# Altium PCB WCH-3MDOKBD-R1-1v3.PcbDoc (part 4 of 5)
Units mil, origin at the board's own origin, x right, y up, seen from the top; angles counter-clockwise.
Board outline 11710.74 x 4477.49 mil, 2 copper layers (Top Layer, Bottom Layer); 422 components, 246 nets, 927 pads, 1295 vias.
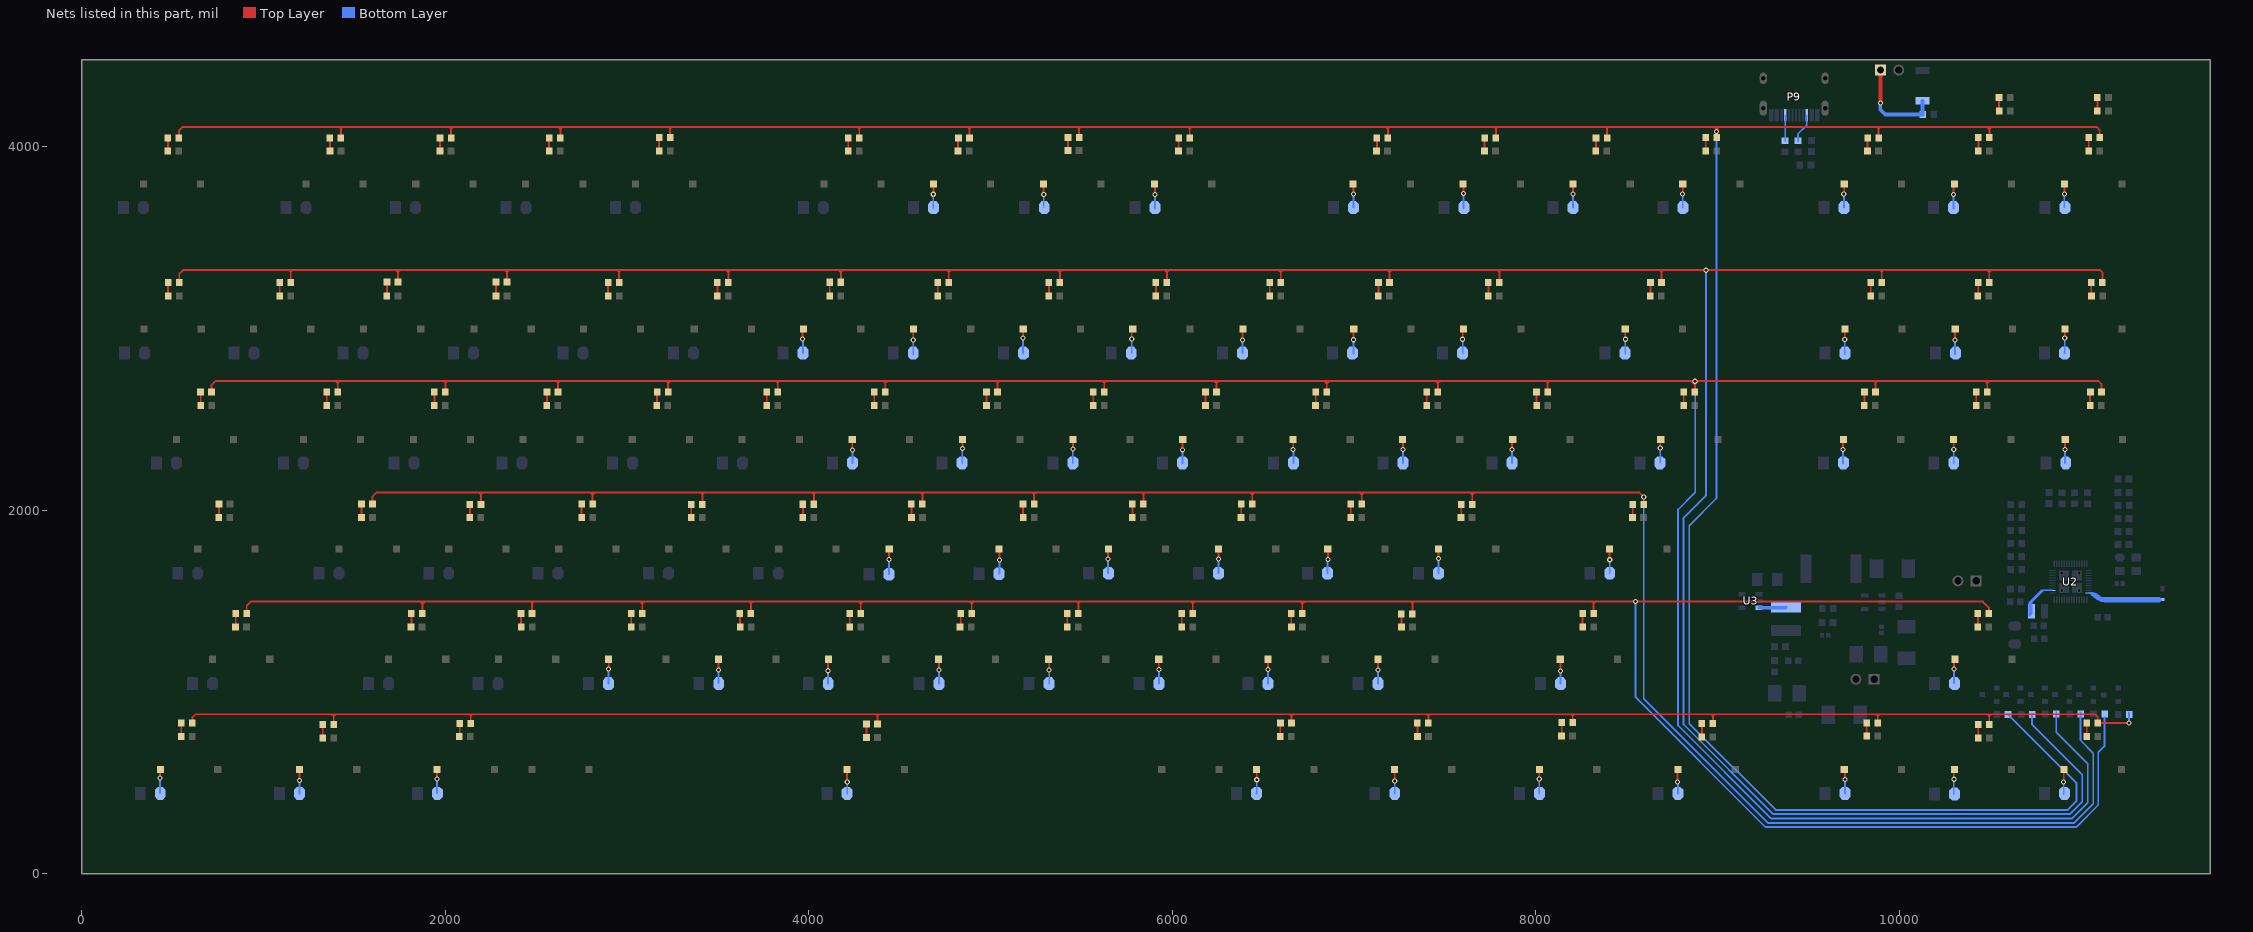
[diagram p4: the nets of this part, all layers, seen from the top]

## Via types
v1: diameter 28, hole 16, Top Layer to Bottom Layer, tented both sides, 1167 vias
v2: diameter 24, hole 12, Top Layer to Bottom Layer, tented both sides, 128 vias

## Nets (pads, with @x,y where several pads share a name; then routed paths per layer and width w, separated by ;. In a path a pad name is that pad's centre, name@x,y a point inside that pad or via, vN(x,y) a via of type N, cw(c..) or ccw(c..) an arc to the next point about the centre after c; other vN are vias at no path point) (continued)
NetD31_1: D31.1 S28.2 | length 134.2
  Top Layer w10: S28.2@2899.53,1178.83 2899.59,1178.76 v1(2899.59,1125.29)
  Bottom Layer w10: D31.1@2898.24,1045.22 2898.24,1123.94 v1(2899.59,1125.29)
NetD32_1: D32.1 S29.2 | length 132.2
  Top Layer w10: v1(3503.65,1120.09) 3503.65,1178.34 S29.2@3504.14,1178.83
  Bottom Layer w10: D32.1@3503.65,1046.84 v1(3503.65,1120.09)
NetD33_1: D33.1 S30.2 | length 131.7
  Top Layer w10: v1(4106.44,1116.13) S30.2@4106.44,1176.51
  Bottom Layer w10: v1(4106.44,1116.13) 4106.44,1046.21 D33.1@4107.43,1045.22
NetD34_1: D34.1 S31.2 | length 141.6
  Top Layer w10: v1(430.8,524.84) S31.2@430.8,584.45
  Bottom Layer w10: D34.1@430.8,442.82 v1(430.8,524.84)
NetD35_1: D35.1 S32.2 | length 152.1
  Top Layer w10: v1(1199.17,511.16) S32.2@1199.17,576.44
  Bottom Layer w10: D35.1@1198.31,440.87 1198.31,519.24 1199.17,518.39 v1(1199.17,511.16)
NetD36_1: D36.1 S33.2 | length 136.4
  Top Layer w10: v1(1955.94,519.52) S33.2@1955.94,578.37
  Bottom Layer w10: D36.1@1955.94,441.98 v1(1955.94,519.52)
NetD37_1: D37.1 S34.2 | length 132.3
  Top Layer w10: S34.2@4211.04,573.38 4211.04,504.55 v1(4211.82,503.77)
  Bottom Layer w10: D37.1@4211.82,441.42 v1(4211.82,503.77)
NetD38_1: D38.1 S35.2 | length 138.5
  Top Layer w10: v1(6464.36,516.16) S35.2@6464.36,579.19
  Bottom Layer w10: D38.1@6464.02,440.87 6464.36,441.22 v1(6464.36,516.16)
NetD39_1: D39.1 S_Fn1.2 | length 129
  Top Layer w10: v1(7223.58,510.3) S_Fn1.2@7223.58,569.84
  Bottom Layer w10: D39.1@7223.58,440.87 v1(7223.58,510.3)
NetD40_1: D40.1 S36.2 | length 132.3
  Top Layer w10: v1(4685.16,3736.92) 4685.86,3737.61 S36.2@4685.86,3793.97
  Bottom Layer w10: D40.1@4685.16,3661.95 v1(4685.16,3736.92)
NetD41_1: D41.1 S37.2 | length 129.4
  Top Layer w10: S37.2@5292.31,3794.25 5292.31,3736.51 v1(5293,3735.82)
  Bottom Layer w10: D41.1@5293,3665.15 v1(5293,3735.82)
NetD42_1: D42.1 S38.2 | length 138.5
  Top Layer w10: v1(5905.07,3735.23) S38.2@5905.07,3796.54
  Bottom Layer w10: D42.1@5905.07,3658.01 D42.1@5905.07,3664.02 v1(5905.07,3735.23)
NetD43_1: D43.1 S39.2 | length 131.5
  Top Layer w10: v1(6997.07,3739.18) S39.2@6997.07,3795.1
  Bottom Layer w10: D43.1@6995.94,3664.02 6995.94,3738.05 v1(6997.07,3739.18)
NetD44_1: D44.1 S40.2 | length 135.5
  Top Layer w10: v1(7601.65,3740.67) S40.2@7601.65,3797.73
  Bottom Layer w10: D44.1@7601.65,3662.26 v1(7601.65,3740.67)
NetD45_1: D45.1 S41.2 | length 130.1
  Top Layer w10: S41.2@8204.62,3793.88 8205.12,3793.38 v1(8205.12,3739.5)
  Bottom Layer w10: v1(8205.12,3739.5) 8205.12,3664.13 D45.1@8205.22,3664.02
NetD46_1: D46.1 S42.2 | length 130.5
  Top Layer w10: v1(8807.11,3739.5) 8807.58,3739.98 S42.2@8807.58,3793.8
  Bottom Layer w10: v1(8807.11,3739.5) 8808.27,3738.34 D46.1@8808.27,3664.02
NetD47_1: D47.1 S43.2 | length 134.3
  Top Layer w10: v1(3966,2941.18) S43.2@3966,2996.88
  Bottom Layer w10: v1(3966,2941.18) 3968.09,2939.09 D47.1@3968.09,2863.47
NetD48_1: D48.1 S44.2 | length 138
  Top Layer w10: v1(4574.85,2936.23) S44.2@4574.85,2992.51
  Bottom Layer w10: D48.1@4574.85,2854.52 D48.1@4574.85,2863.47 v1(4574.85,2936.23)
NetD49_1: D49.1 S45.2 | length 132.2
  Top Layer w10: v1(5179.6,2945.87) 5180.45,2946.72 S45.2@5180.45,2994.96
  Bottom Layer w10: v1(5179.6,2945.87) 5179.6,2864.34 D49.1@5180.47,2863.47
NetD50_1: D50.1 S46.2 | length 132.7
  Top Layer w10: v1(5776.74,2941.88) S46.2@5776.74,2994.99
  Bottom Layer w10: D50.1@5776.74,2862.31 v1(5776.74,2941.88)
NetD51_1: D51.1 S47.2 | length 139.1
  Top Layer w10: v1(6386.92,2936.4) S47.2@6386.92,3002.61
  Bottom Layer w10: D51.1@6386.92,2863.47 v1(6386.92,2936.4)
NetD52_1: D52.1 S48.2 | length 131.6
  Top Layer w10: v1(6996.14,2936.51) S48.2@6996.14,2993.09
  Bottom Layer w10: D52.1@6996.14,2861.45 v1(6996.14,2936.51)
NetD53_1: D53.1 S49.2 | length 134.9
  Top Layer w10: v1(7597.41,2939.64) S49.2@7597.41,2998.3
  Bottom Layer w10: D53.1@7597.3,2863.47 7597.41,2863.58 v1(7597.41,2939.64)
NetD54_1: D54.1 S50.2 | length 129.8
  Top Layer w10: S50.2@4239.53,2388.74 4239.53,2330.43 v1(4240.01,2329.95)
  Bottom Layer w10: D54.1@4239.96,2259.16 4240.01,2259.21 v1(4240.01,2329.95)
NetD55_1: D55.1 S51.2 | length 136.4
  Top Layer w10: v1(4845.53,2338.81) 4846.37,2339.65 S51.2@4846.37,2388.74 S51.2@4846.37,2394.62
  Bottom Layer w10: D55.1@4844.14,2259.16 4844.14,2337.42 v1(4845.53,2338.81)
NetD56_1: D56.1 S52.2 | length 129.1
  Top Layer w10: v1(5454.29,2335.45) S52.2@5454.29,2387.68
  Bottom Layer w10: D56.1@5452.8,2259.16 5452.8,2333.96 v1(5454.29,2335.45)
NetD57_1: D57.1 S53.2 | length 132
  Top Layer w10: v1(6055.6,2331.35) S53.2@6055.6,2391.13
  Bottom Layer w10: D57.1@6055.6,2259.16 v1(6055.6,2331.35)
NetD58_1: D58.1 S54.2 | length 130.5
  Top Layer w10: S54.2@6664.28,2388.74 6664.94,2388.08 v1(6664.94,2332.01)
  Bottom Layer w10: v1(6664.94,2332.01) 6666.44,2330.51 D58.1@6666.44,2259.16
NetD59_1: D59.1 S55.2 | length 133.2
  Top Layer w10: v1(7269,2331.93) S55.2@7269,2392.28
  Bottom Layer w10: v1(7269,2331.93) 7269,2259.3 D59.1@7269.14,2259.16
NetD60_1: D60.1 S56.2 | length 136.9
  Top Layer w10: S56.2@7869.08,2390.47 v1(7869.08,2333.53) v1@7873.05,2337.49
  Bottom Layer w10: D60.1@7869.08,2259.16 7869.08,2281.77 v1(7869.08,2333.53)
NetD61_1: D61.1 S57.2 | length 140.1
  Top Layer w10: v1(4442.36,1726.86) S57.2@4442.36,1786.71
  Bottom Layer w10: D61.1@4442.3,1646.61 4442.3,1726.8 v1(4442.36,1726.86)
NetD62_1: D62.1 S58.2 | length 137.8
  Top Layer w10: v1(5048.62,1725.98) S58.2@5048.62,1787.21
  Bottom Layer w10: D62.1@5047.11,1650.08 5048.62,1651.59 v1(5048.62,1725.98)
NetD63_1: D63.1 S59.2 | length 138.9
  Top Layer w10: v1(5646.28,1731) S59.2@5646.28,1793.07
  Bottom Layer w10: D63.1@5646.28,1654.16 v1(5646.28,1731)
NetD64_1: D64.1 S60.2 | length 133.9
  Top Layer w10: S60.2@6253.89,1785.35 6254.37,1784.87 v1(6254.37,1730.62)
  Bottom Layer w10: D64.1@6253.38,1652.04 6254.37,1653.03 v1(6254.37,1730.62)
NetD65_1: D65.1 S61.2 | length 133.7
  Top Layer w10: S61.2@6855.58,1785.35 6856.19,1784.74 v1(6856.19,1728.46)
  Bottom Layer w10: D65.1@6854.15,1651.91 v1@6854.15,1728.46
NetD66_1: D66.1 S62.2 | length 134.1
  Top Layer w10: S62.2@7464,1785.35 7464.51,1784.84 v1(7464.51,1732.79)
  Bottom Layer w10: D66.1@7463.53,1651.91 7464.51,1652.89 v1(7464.51,1732.79)
NetD67_1: D67.1 S63.2 | length 129
  Top Layer w10: v1(8684.1,2341.25) S63.2@8684.1,2390.07
  Bottom Layer w10: D67.1@8684.1,2261.08 v1(8684.1,2341.25)
NetD68_1: D68.1 S64.2 | length 138.3
  Top Layer w10: v1(4717.14,1120.08) S64.2@4717.14,1183.5
  Bottom Layer w10: D68.1@4717.14,1045.22 v1(4717.14,1120.08)
NetD69_1: D69.1 S65.2 | length 135.2
  Top Layer w10: v1(5322.73,1120.41) S65.2@5322.73,1180.38
  Bottom Layer w10: D69.1@5322.73,1045.22 v1(5322.73,1120.41)
NetD70_1: D70.1 S66.2 | length 134.1
  Top Layer w10: S66.2@5925.44,1178.83 5925.44,1124.13 v1(5926.55,1123.02)
  Bottom Layer w10: D70.1@5926.55,1045.22 v1(5926.55,1123.02)
NetD71_1: D71.1 S67.2 | length 133.9
  Top Layer w10: v1(6526.43,1122.05) S67.2@6526.44,1178.83
  Bottom Layer w10: D71.1@6525.65,1045.22 6526.43,1046 v1(6526.43,1122.05)
NetD72_1: D72.1 S68.2 | length 139.9
  Top Layer w10: v1(7131.13,1120.14) S68.2@7131.13,1179.43
  Bottom Layer w10: D72.1@7131.13,1045.22 v1(7131.13,1120.14) v1@7135.17,1116.1
NetD73_1: D73.1 S69.2 | length 135.6
  Top Layer w10: v1(8136.22,1113.6) S69.2@8136.22,1180.83
  Bottom Layer w10: D73.1@8136.22,1045.22 v1(8136.22,1113.6)
NetD74_1: D74.1 S71.2 | length 137.6
  Top Layer w10: v1(8018.47,521.24) S71.2@8018.47,578.32
  Bottom Layer w10: D74.1@8018.47,440.69 v1(8018.47,521.24)
NetD75_1: D75.1 S72.2 | length 134.3
  Top Layer w10: v1(8779.58,503.77) S72.2@8779.58,574.48
  Bottom Layer w10: v1(8779.58,503.77) 8781.21,502.13 8781.21,446.71 D75.1@8781.21,440.87
NetD76_1: D76.1 S73.2 | length 131.3
  Top Layer w10: v1(9693.64,3738.1) 9696.07,3740.53 S73.2@9696.07,3793.8
  Bottom Layer w10: v1(9693.64,3738.1) 9694.83,3736.91 D76.1@9694.83,3664.02
NetD77_1: D77.1 S74.2 | length 139.3
  Top Layer w10: v1(10297.44,3736.7) S74.2@10297.44,3797.73
  Bottom Layer w10: D77.1@10297.44,3658.43 D77.1@10297.44,3664.02 v1(10297.44,3736.7)
NetD78_1: D78.1 S75.2 | length 127.7
  Top Layer w10: v1(10906.92,3739.33) 10908.61,3741.01 S75.2@10908.61,3793.8
  Bottom Layer w10: D78.1@10906.92,3666.78 v1(10906.92,3739.33)
NetD79_1: D79.1 S76.2 | length 133.5
  Top Layer w10: S76.2@8491.69,2994.96 8491.69,2940.01 v1(8492.05,2939.64)
  Bottom Layer w10: D79.1@8492.05,2861.63 v1(8492.05,2939.64)
NetD80_1: D80.1 S77.2 | length 136
  Top Layer w10: v1(9699.13,2938.04) S77.2@9699.13,2994.22
  Bottom Layer w10: D80.1@9699.13,2858.2 v1(9699.13,2938.04)
NetD81_1: D81.1 S78.2 | length 137
  Top Layer w10: v1(10305.64,2935.27) S78.2@10305.64,2996.14
  Bottom Layer w10: D81.1@10305.64,2859.11 v1(10305.64,2935.27)
NetD82_1: D82.1 S79.2 | length 139
  Top Layer w10: v1(10909.21,2945.36) S79.2@10909.21,3002.25
  Bottom Layer w10: D82.1@10908.74,2863.47 10909.21,2863.94 v1(10909.21,2945.36)
NetD83_1: D83.1 S80.2 | length 135.1
  Top Layer w10: v1(9688.8,2332.41) S80.2@9688.8,2390.15
  Bottom Layer w10: D83.1@9688.8,2255.02 v1(9688.8,2332.41)
NetD84_1: D84.1 S81.2 | length 130.8
  Top Layer w10: v1(10298.64,2332.73) S81.2@10298.64,2390
  Bottom Layer w10: D84.1@10298.64,2259.16 v1(10298.64,2332.73)
NetD85_1: D85.1 S82.2 | length 133.1
  Top Layer w10: v1(10911.34,2332.49) S82.2@10911.34,2390.03
  Bottom Layer w10: D85.1@10911.34,2256.9 v1(10911.34,2332.49)
NetD86_1: D86.1 S83.2 | length 133.7
  Top Layer w10: S83.2@8405.85,1785.35 8405.85,1726.62 v1(8406.18,1726.29)
  Bottom Layer w10: v1(8406.18,1726.29) 8406.18,1652.29 D86.1@8406.56,1651.91
NetD87_1: D87.1 S84.2 | length 135.8
  Top Layer w10: v1(10300.88,1125.06) S84.2@10300.88,1184.04
  Bottom Layer w10: D87.1@10300.88,1048.24 v1(10300.88,1125.06)
NetD88_1: D88.1 S85.2 | length 136.4
  Top Layer w10: v1(9700.87,518.17) S85.2@9700.87,577.23
  Bottom Layer w10: D88.1@9700.87,440.87 v1(9700.87,518.17)
NetD89_1: D89.1 S86.2 | length 139.9
  Top Layer w10: v1(10299.17,518.96) S86.2@10299.17,577.16
  Bottom Layer w10: D89.1@10299.17,437.25 v1(10299.17,518.96)
NetD90_1: D90.1 S87.2 | length 146.3
  Top Layer w10: v1(10903.4,503.78) S87.2@10903.4,584.89
  Bottom Layer w10: D90.1@10903.4,438.59 v1(10903.4,503.78)
NetD199_K: D199.K R104.1 | length 74.2
  Top Layer w10: D199.K@10431.48,1355.99 R104.1@10431.48,1430.13
NetD227_K: D227.K R122.1 | length 71.4
  Top Layer w10: D227.K@9820.51,758.27 R122.1@9820.51,829.67
NetD228_K: D228.K R123.1 | length 73.3
  Top Layer w10: D228.K@10433.47,747.72 R123.1@10433.47,821.07
NetD229_K: D229.K R124.1 | length 73.4
  Top Layer w10: D229.K@11030.33,754.67 11030.68,755.02 R124.1@11030.68,827.9
NetE1_1: E1.1 U2.34 | length 564.8
  Bottom Layer w7: 11075.28,1527.52 11070.76,1532.04 ccw(c11042.5,1503.78) U2.34@11042.5,1543.75 ; 11077.67,1516.72 11056.4,1537.99 ccw(c11042.5,1524.09) U2.34@11042.5,1543.75 ; 11083.07,1526.21 11081.81,1527.47 ccw(c11042.5,1488.16) U2.34@11042.5,1543.75 ; 11083.9,1530.76 ccw(c11052.55,1499.41) U2.34@11052.55,1543.75 ; 11091.68,1532.51 ccw(c11064.53,1505.36) 11064.53,1543.75 U2.34@11052.55,1543.75 ; U2.34@11042.5,1543.75 U2.34@11052.55,1543.75
  Bottom Layer w28.1: 11083.07,1526.21 ccw(c11131.36,1574.5) 11131.36,1506.2 11426.79,1506.2
NetL2_1: L2.1 U2.2 | length 637.6
  Bottom Layer w7: 10794.37,1557.49 10791.14,1557.49 ; U2.2@10841.57,1557.49 10791.14,1557.49 ; L2.1@10714.85,1431.78 10721.99,1424.64 L2.1@10722.52,1424.64 ; L2.1@10714.85,1431.78 L2.1@10714.85,1439.54 ; L2.1@10714.85,1431.78 10714.85,1416.98 L2.1@10722.52,1424.64 ; L2.1@10714.85,1431.78 L2.1@10722.52,1439.45 ; L2.1@10714.85,1439.54 L2.1@10714.85,1454.87 ; L2.1@10714.85,1439.54 L2.1@10722.52,1447.21 ; L2.1@10714.85,1454.87 L2.1@10722.52,1462.54 ; L2.1@10714.85,1454.87 L2.1@10714.85,1470.21 ; L2.1@10714.85,1454.87 L2.1@10722.52,1447.21 ; L2.1@10714.85,1470.21 10721.96,1477.32 L2.1@10722.52,1477.32 ; L2.1@10714.85,1470.21 L2.1@10714.85,1473.53 ; L2.1@10714.85,1470.21 L2.1@10722.52,1462.54 ; L2.1@10714.85,1473.53 10714.85,1488.87 ; L2.1@10714.85,1473.53 L2.1@10722.52,1481.2 ; 10714.85,1488.87 L2.1@10722.52,1481.2 ; 10714.85,1488.87 10722.52,1488.87 ; 10714.85,1488.87 10783.47,1557.49 10791.14,1557.49 ; L2.1@10722.52,1424.64 L2.1@10722.52,1439.45 ; L2.1@10722.52,1424.64 10728.64,1430.77 L2.1@10728.64,1445.57 ; L2.1@10722.52,1439.45 L2.1@10722.52,1447.21 ; L2.1@10722.52,1439.45 L2.1@10726.4,1443.33 ; L2.1@10722.52,1447.21 L2.1@10722.52,1462.54 ; L2.1@10722.52,1447.21 L2.1@10726.4,1443.33 ; L2.1@10722.52,1462.54 L2.1@10722.52,1477.32 ; L2.1@10722.52,1477.32 L2.1@10722.52,1481.2 ; L2.1@10722.52,1477.32 L2.1@10726.4,1477.32 ; L2.1@10722.52,1481.2 10722.52,1488.87 ; L2.1@10722.52,1481.2 L2.1@10726.4,1477.32 ; 10722.52,1488.87 10728.64,1494.99 ; L2.1@10726.4,1443.33 L2.1@10728.64,1445.57 ; L2.1@10726.4,1443.33 L2.1@10726.4,1477.32 ; L2.1@10728.64,1445.57 10728.64,1494.99 ; 10728.64,1494.99 10791.14,1557.49
NetL4_1: L4.1 U3.3 | length 147.6
  Bottom Layer w20: U3.3@9228.06,1462.52 9372.73,1462.52 L4.1@9374.78,1464.57
NetLD7_K: LD7.K R2.1 | length 71.8
  Top Layer w10: LD7.K@474.68,3974.68 474.9,3974.9 R2.1@474.9,4046.43
NetLD8_K: LD8.K R3.1 | length 72.6
  Top Layer w10: R3.1@1365.64,4047.02 1366.4,4046.26 LD8.K@1366.4,3974.68
NetLD9_K: LD9.K R4.1 | length 73.4
  Top Layer w10: LD9.K@1971.56,3974.68 1971.56,4047.31 R4.1@1972.09,4047.85
NetLD10_K: LD10.K R5.1 | length 72.2
  Top Layer w10: LD10.K@2571.96,3974.68 2571.96,4044.95 R5.1@2573.31,4046.3
NetLD11_K: LD11.K R6.1 | length 74.5
  Top Layer w10: R6.1@3176.94,4049.03 3177.26,4048.72 LD11.K@3177.26,3974.68
NetLD12_K: LD12.K R7.1 | length 71.7
  Top Layer w10: LD12.K@4217.68,3974.79 R7.1@4217.68,4046.45
NetLD13_K: LD13.K R8.1 | length 69
  Top Layer w10: LD13.K@4821.52,3974.68 R8.1@4821.52,4043.67
NetLD14_K: LD14.K R9.1 | length 72
  Top Layer w10: LD14.K@5426.5,3977.21 5426.5,4048.98 R9.1@5426.68,4049.16
NetLD15_K: LD15.K R10.1@6035.26,4046.93 | length 72.5
  Top Layer w10: LD15.K@6034.54,3974.68 6035.26,3975.41 R10.1@6035.26,4046.93
NetLD16_K: LD16.K R11.1@7125.5,4047.46 | length 76
  Top Layer w10: LD16.K@7125.5,3971.43 R11.1@7125.5,4047.46
NetLD17_K: LD17.K R12.1 | length 76.5
  Top Layer w10: LD17.K@7717.43,3974.68 R12.1@7717.43,4051.23
NetLD18_K: LD18.K R13.1 | length 70.2
  Top Layer w10: LD18.K@8331.16,3975.8 R13.1@8331.16,4046.03
NetLD19_K: LD19.K R14.1 | length 75.1
  Top Layer w10: LD19.K@8934.28,3974.68 8934.65,3975.05 R14.1@8934.65,4049.64
NetLD21_K: LD21.K R16.1 | length 72.1
  Top Layer w10: LD21.K@9824.58,3974.68 9824.78,3974.89 R16.1@9824.78,4046.75
NetLD22_K: LD22.K R17.1 | length 73.5
  Top Layer w10: LD22.K@10433.33,3975.24 10434.11,3976.01 R17.1@10434.11,4048.46
NetLD23_K: LD23.K R18.1 | length 72.1
  Top Layer w10: LD23.K@11041.54,3976.13 11041.59,3976.18 R18.1@11041.59,4048.25
NetLD52_K: LD52.K R25.1 | length 73.7
  Top Layer w10: LD52.K@476.33,3178.04 476.33,3251.46 R25.1@476.53,3251.67
NetLD53_K: LD53.K R26.1 | length 76.7
  Top Layer w10: LD53.K@1090.21,3175.94 R26.1@1090.21,3252.61
NetLD54_K: LD54.K R27.1 | length 75.1
  Top Layer w10: LD54.K@1679.73,3178.04 1679.96,3178.26 R27.1@1679.96,3253.07
NetLD55_K: LD55.K R28.1 | length 75.3
  Top Layer w10: LD55.K@2279.43,3178.04 2279.96,3178.57 R28.1@2279.96,3253.12
NetLD56_K: LD56.K R29.1 | length 74.2
  Top Layer w10: R29.1@2896.29,3252.16 2896.29,3178.32 LD56.K@2896.58,3178.04
NetLD57_K: LD57.K R30.1 | length 74.9
  Top Layer w10: LD57.K@3497.58,3178.04 R30.1@3497.58,3252.88
NetLD58_K: LD58.K R31.1 | length 75
  Top Layer w10: LD58.K@4116.08,3178.04 4116.17,3178.13 R31.1@4116.17,3253.05
NetLD59_K: LD59.K R32.1 | length 74.8
  Top Layer w10: R32.1@4709.97,3252.74 4709.97,3178.34 LD59.K@4710.27,3178.04
NetLD60_K: LD60.K R33.1 | length 73.5
  Top Layer w10: LD60.K@5321.22,3178.54 R33.1@5321.22,3252.04
NetLD61_K: LD61.K R34.1 | length 74.6
  Top Layer w10: LD61.K@5908.69,3178.04 5909.54,3178.89 R34.1@5909.54,3252.33
NetLD62_K: LD62.K R35.1 | length 74.6
  Top Layer w10: LD62.K@6535.57,3178.04 6535.68,3178.15 R35.1@6535.68,3252.61
NetLD63_K: LD63.K R36.1 | length 74.9
  Top Layer w10: LD63.K@7133.46,3178.04 7134.17,3178.75 R36.1@7134.17,3252.61
NetLD64_K: LD64.K R37.1 | length 74.8
  Top Layer w10: LD64.K@7738.63,3177.78 R37.1@7738.63,3252.61
NetLD65_K: LD65.K R38.1 | length 75.1
  Top Layer w10: LD65.K@8629.08,3178.04 8630.24,3179.19 R38.1@8630.24,3252.61
NetLD66_K: LD66.K R39.1 | length 74.3
  Top Layer w10: LD66.K@9841.96,3178.04 9842,3178.08 R39.1@9842,3252.32
NetLD67_K: LD67.K R40.1 | length 78.9
  Top Layer w10: LD67.K@10433.26,3173.68 R40.1@10433.26,3252.61
NetLD68_K: LD68.K R41.1 | length 77.8
  Top Layer w10: LD68.K@11055.61,3174.85 R41.1@11055.61,3252.61
NetLD93_K: LD93.K R48.1 | length 73
  Top Layer w10: R48.1@654.54,2648.31 655.14,2647.71 LD93.K@655.14,2575.56
NetLD94_K: LD94.K R49.1 | length 72.8
  Top Layer w10: LD94.K@1348.76,2575.56 R49.1@1348.76,2648.31
NetLD95_K: LD95.K R50.1 | length 74.6
  Top Layer w10: LD95.K@1939.59,2575.56 1940.9,2576.87 R50.1@1940.9,2649.63
NetLD96_K: LD96.K R51.1 | length 72.9
  Top Layer w10: LD96.K@2560.01,2576.29 R51.1@2560.01,2649.18
NetLD97_K: LD97.K R52.1 | length 71.1
  Top Layer w10: LD97.K@3166.04,2576.97 R52.1@3166.04,2648.1
NetLD98_K: LD98.K R53.1 | length 73.4
  Top Layer w10: LD98.K@3768.5,2575.56 3768.87,2575.92 R53.1@3768.87,2648.8
NetLD99_K: LD99.K R54.1 | length 72.8
  Top Layer w10: LD99.K@4360.67,2575.56 R54.1@4360.67,2648.31
NetLD100_K: LD100.K R55.1 | length 72.7
  Top Layer w10: LD100.K@4978.02,2575.86 R55.1@4978.02,2648.54
NetLD101_K: LD101.K R56.1 | length 73.1
  Top Layer w10: LD101.K@5564.71,2575.56 5564.94,2575.78 R56.1@5564.94,2648.53
NetLD102_K: LD102.K R57.1 | length 72.8
  Top Layer w10: LD102.K@6182.61,2575.56 R57.1@6182.61,2648.31
NetLD103_K: LD103.K R58.1 | length 73.1
  Top Layer w10: LD103.K@6787.88,2575.56 6788.76,2576.45 R58.1@6788.76,2648.31
NetLD104_K: LD104.K R59.1 | length 73
  Top Layer w10: LD104.K@7399.63,2575.56 7400.14,2576.06 R59.1@7400.14,2648.31
NetLD105_K: LD105.K R60.1 | length 76.5
  Top Layer w10: LD105.K@8003.81,2571.86 R60.1@8003.81,2648.31
NetLD106_K: LD106.K R61.1 | length 73.7
  Top Layer w10: LD106.K@8813.92,2575.56 8813.92,2649.04 R61.1@8814.07,2649.19
NetLD107_K: LD107.K R62.1 | length 77.5
  Top Layer w10: LD107.K@9807.62,2570.81 R62.1@9807.62,2648.31
NetLD108_K: LD108.K R63.1 | length 72.8
  Top Layer w10: LD108.K@10422.29,2575.56 10422.52,2575.78 R63.1@10422.52,2648.31
NetLD109_K: LD109.K R64.1 | length 75.6
  Top Layer w10: LD109.K@11049.08,2575.56 R64.1@11049.08,2651.2
NetLD140_K: LD140.K R72.1 | length 73.2
  Top Layer w10: R72.1@1539.53,2031.99 1539.53,1959.23 LD140.K@1539.83,1958.93
NetLD141_K: LD141.K R73.1 | length 72.3
  Top Layer w10: LD141.K@2135.58,1958.93 2136.29,1959.64 R73.1@2136.29,2030.9
NetLD142_K: LD142.K R74.1 | length 71.9
  Top Layer w10: LD142.K@2750.71,1960.12 R74.1@2750.71,2032.03
NetLD143_K: LD143.K R75.1 | length 72.5
  Top Layer w10: R75.1@3354.25,2031.41 3354.25,1959.05 LD143.K@3354.37,1958.93
NetLD144_K: LD144.K R76.1 | length 71.8
  Top Layer w10: LD144.K@3967.62,1960.07 3967.83,1960.27 R76.1@3967.83,2031.83
NetLD145_K: LD145.K R77.1 | length 74
  Top Layer w10: R77.1@4564.59,2033.84 4564.59,1960.37 LD145.K@4564.97,1959.98
NetLD146_K: LD146.K R78.1 | length 76.8
  Top Layer w10: LD146.K@5179.18,1957.21 R78.1@5179.18,2034.04
NetLD147_K: LD147.K R79.1 | length 74.3
  Top Layer w10: LD147.K@5779.62,1958.93 5780.5,1959.82 R79.1@5780.5,2032.89
NetLD148_K: LD148.K R80.1 | length 74.5
  Top Layer w10: LD148.K@6378.37,1958.93 6379.58,1960.14 R80.1@6379.58,2032.89
NetLD149_K: LD149.K R81.1 | length 74.2
  Top Layer w10: LD149.K@6981.14,1958.93 6981.64,1959.43 R81.1@6981.64,2032.88
NetLD150_K: LD150.K R82.1 | length 69.7
  Top Layer w10: LD150.K@7589.34,1960.02 R82.1@7589.34,2029.77
NetLD151_K: LD151.K R83.1 | length 73.1
  Top Layer w10: LD151.K@8531.67,1958.93 8532.99,1960.24 R83.1@8532.99,2031.46
NetLD186_K: LD186.K R91.1 | length 76
  Top Layer w10: LD186.K@847.94,1354.15 R91.1@847.94,1430.13
NetLD187_K: LD187.K R92.1 | length 75.4
  Top Layer w10: LD187.K@1814.29,1354.78 R92.1@1814.29,1430.13
NetLD188_K: LD188.K R93.1 | length 72.6
  Top Layer w10: LD188.K@2417.39,1357.5 R93.1@2417.39,1430.13
NetLD189_K: LD189.K R94.1 | length 74.5
  Top Layer w10: LD189.K@3022.9,1355.98 3023.78,1356.86 R94.1@3023.78,1430.13
NetLD190_K: LD190.K R95.1 | length 74.7
  Top Layer w10: R95.1@3621.34,1430.13 3621.34,1357.34 LD190.K@3622.71,1355.98
NetLD191_K: LD191.K R96.1 | length 74.5
  Top Layer w10: LD191.K@4224.86,1355.98 4225.6,1356.71 R96.1@4225.6,1430.13
NetLD192_K: LD192.K R97.1 | length 76.8
  Top Layer w10: LD192.K@4836.65,1353.31 R97.1@4836.65,1430.13
NetLD193_K: LD193.K R98.1 | length 74.3
  Top Layer w10: R98.1@5422.61,1430.13 5422.61,1356.31 LD193.K@5422.94,1355.98
NetLD194_K: LD194.K R99.1 | length 74.2
  Top Layer w10: LD194.K@6052.01,1355.98 R99.1@6052.01,1430.13
NetLD195_K: LD195.K R100.1 | length 75.1
  Top Layer w10: R100.1@6654.64,1430.5 6654.64,1357.31 LD195.K@6655.98,1355.98
NetLD196_K: LD196.K R101.1 | length 72.2
  Top Layer w10: R101.1@7260.23,1428.03 7260.23,1356.45 LD196.K@7260.7,1355.98
NetLD197_K: LD197.K R102.1 | length 74.2
  Top Layer w10: LD197.K@8257.08,1355.98 R102.1@8257.08,1430.13
NetLD216_K: LD216.K R111.1 | length 74.4
  Top Layer w10: R111.1@548.72,828.35 548.72,754.32 LD216.K@549.02,754.02
NetLD217_K: LD217.K R112.1 | length 74.3
  Top Layer w10: LD217.K@1326.33,745.9 R112.1@1326.33,820.21
NetLD218_K: LD218.K R113.1 | length 70.6
  Top Layer w10: LD218.K@2080.1,756.11 R113.1@2080.1,826.72
NetLD219_K: LD219.K R114.1 | length 72.9
  Top Layer w10: LD219.K@4317.92,749.84 R114.1@4317.94,822.75
NetLD220_K: LD220.K R115.1 | length 73.3
  Top Layer w10: LD220.K@6594.25,754.78 R115.1@6594.25,828.12
NetLD223_K: LD223.K R118.1 | length 74.7
  Top Layer w10: LD223.K@8142.55,755.92 R118.1@8142.55,830.64
NetLD224_K: LD224.K R119.1 | length 72.6
  Top Layer w10: LD224.K@8913.06,753.52 R119.1@8913.06,826.13
NetLD230_K: LD230.K R126.1 | length 73.4
  Top Layer w10: LD230.K@10548.07,4268.49 10548.07,4195.54 R126.1@10548.37,4195.24
NetLD231_K: LD231.K R127.1 | length 76.8
  Top Layer w10: LD231.K@755.91,1956.92 R127.1@755.91,2033.74
NetLD232_K: LD232.K R135.1 | length 73.3
  Top Layer w10: LD232.K@11088.97,4268.49 11088.97,4195.3 R135.1@11089.03,4195.24
NetLD_Fn_K: LD_Fn.K R_Fn.1 | length 74.1
  Top Layer w10: R_Fn.1@7348.18,828.57 7348.18,755.45 LD_Fn.K@7348.85,754.78
NetP6_1: P6.1 R300.1 S70.1 | length 540.4
  Top Layer w20: v1@9896.11,4240.06 P6.1@9896.11,4420.24
  Bottom Layer w20: v1@9894.17,4241.92 9894.17,4203.59 9922.1,4175.66 R300.1@10128.51,4175.66 10127.09,4177.09 S70.1@10127.09,4251.02
  other v1: 9894.77,4240.06
NetP9_A5: P9.A5 R10.1@9370.04,4031.44 | length 143.5
  Bottom Layer w10: R10.1@9372.01,4028.69 P9.A5@9372.01,4172.15
NetP9_B5: P9.B5 R11.1@9442.13,4032.34 | length 163.5
  Bottom Layer w10: R11.1@9442.13,4028.55 R11.1@9442.13,4032.34 9442.13,4068.95 9490.12,4116.94 P9.B5@9490.12,4172.15
NetR1_1: R1.1 R2.2 R3.2 R4.2 R5.2 R6.2 R7.2 R8.2 R9.2 R10.2@6095.89,4046.93 R11.2@7186.13,4047.46 R12.2 R13.2 R14.2 R16.2 R17.2 R18.2 | length 18257.2
  Top Layer w10: R2.2@535.53,4046.43 535.53,4086.4 556.9,4107.77 1416,4107.77 ; R3.2@1426.27,4047.02 1426.27,4097.5 ; R4.2@2032.72,4047.85 2032.72,4096.86 ; R5.2@2633.94,4046.3 2633.94,4095.75 ; R6.2@3237.57,4049.03 3237.57,4098.04 ; R7.2@4278.31,4046.45 4278.31,4097.41 ; R8.2@4884.21,4045.73 4884.21,4097.99 ; R9.2@5487.31,4049.16 5487.31,4097.77 ; R10.2@6095.89,4046.93 6095.89,4097.4 ; R11.2@7186.13,4047.46 7186.13,4096.44 ; R12.2@7780.09,4045.31 7780.09,4098.36 ; R13.2@8391.79,4046.03 8391.79,4098.61 ; R14.2@8995.28,4049.64 v1@8995.28,4093.22 ; R16.2@9885.41,4046.75 9885.41,4096.3 ; R17.2@10494.74,4048.46 10494.74,4094.1 ; R18.2@11102.22,4048.25 11102.22,4089.92 11084.37,4107.77 10508.4,4107.77 ; 1416,4107.77 1426.42,4107.77 ; 1416,4107.77 1426.27,4097.5 ; 1426.27,4097.5 1436.54,4107.77 ; 1426.27,4097.5 1426.27,4107.62 1426.42,4107.77 ; 1426.42,4107.77 1436.54,4107.77 ; 1436.54,4107.77 2023.54,4107.77 ; 2023.54,4107.77 2034.94,4107.77 ; 2023.54,4107.77 2023.54,4106.05 2032.72,4096.86 ; 2032.72,4096.86 2043.63,4107.77 ; 2032.72,4096.86 2032.72,4105.55 2034.94,4107.77 ; 2034.94,4107.77 2043.63,4107.77 ; 2043.63,4107.77 2621.92,4107.77 ; 2621.92,4107.77 2634.98,4107.77 ; 2621.92,4107.77 2633.94,4095.75 ; 2633.94,4095.75 2645.95,4107.77 ; 2633.94,4095.75 2633.94,4106.72 2634.98,4107.77 ; 2634.98,4107.77 2645.95,4107.77 ; 2645.95,4107.77 3227.85,4107.77 ; 3227.85,4107.77 3239.14,4107.77 ; 3227.85,4107.77 3237.57,4098.04 ; 3237.57,4098.04 3247.3,4107.77 ; 3237.57,4098.04 3237.57,4106.2 3239.14,4107.77 ; 3239.14,4107.77 3247.3,4107.77 ; 3247.3,4107.77 4267.96,4107.77 ; 4267.96,4107.77 4280.23,4107.77 ; 4267.96,4107.77 4278.31,4097.41 ; 4278.31,4097.41 4288.67,4107.77 ; 4278.31,4097.41 4278.31,4105.85 4280.23,4107.77 ; 4280.23,4107.77 4288.67,4107.77 ; 4288.67,4107.77 4874.43,4107.77 ; 4874.43,4107.77 4885.68,4107.77 ; 4874.43,4107.77 4884.21,4097.99 ; 4884.21,4097.99 4893.99,4107.77 ; 4884.21,4097.99 4884.21,4106.3 4885.68,4107.77 ; 4885.68,4107.77 4893.99,4107.77 ; 4893.99,4107.77 5477.31,4107.77 ; 5477.31,4107.77 5488.91,4107.77 ; 5477.31,4107.77 5487.31,4097.77 ; 5487.31,4097.77 5497.31,4107.77 ; 5487.31,4097.77 5487.31,4106.17 5488.91,4107.77 ; 5488.91,4107.77 5497.31,4107.77 ; 5497.31,4107.77 6085.52,4107.77 ; 6085.52,4107.77 6095.51,4107.77 ; 6085.52,4107.77 6095.89,4097.4 ; 6095.51,4107.77 6106.26,4107.77 ; 6095.51,4107.77 6095.89,4107.39 6095.89,4097.4 ; 6095.89,4097.4 6106.26,4107.77 ; 6106.26,4107.77 7174.8,4107.77 ; 7174.8,4107.77 7183.24,4107.77 ; 7174.8,4107.77 7186.13,4096.44 ; 7183.24,4107.77 7197.46,4107.77 ; 7183.24,4107.77 7186.13,4104.87 7186.13,4096.44 ; 7186.13,4096.44 7197.46,4107.77 ; 7197.46,4107.77 7770.69,4107.77 ; 7770.69,4107.77 7779.43,4107.77 ; 7770.69,4107.77 7780.09,4098.36 ; 7779.43,4107.77 7789.5,4107.77 ; 7779.43,4107.77 7780.09,4107.1 7780.09,4098.36 ; 7780.09,4098.36 7789.5,4107.77 ; 7789.5,4107.77 8382.63,4107.77 ; 8382.63,4107.77 8393.51,4107.77 ; 8382.63,4107.77 8391.79,4098.61 ; 8391.79,4098.61 8393.08,4098.61 8402.24,4107.77 ; 8391.79,4098.61 8391.79,4106.05 8393.51,4107.77 ; 8393.51,4107.77 8402.24,4107.77 ; 8402.24,4107.77 8980.74,4107.77 ; 8980.74,4107.77 8996.08,4107.77 ; 8980.74,4107.77 v1@8995.28,4093.22 ; v1@8995.28,4093.22 9009.83,4107.77 ; v1@8995.28,4093.22 8995.28,4106.97 8996.08,4107.77 ; 8996.08,4107.77 9009.83,4107.77 ; 9009.83,4107.77 9873.94,4107.77 ; 9873.94,4107.77 9886.68,4107.77 ; 9873.94,4107.77 9885.41,4096.3 ; 9885.41,4096.3 9896.88,4107.77 ; 9885.41,4096.3 9885.41,4106.5 9886.68,4107.77 ; 9886.68,4107.77 9896.88,4107.77 ; 9896.88,4107.77 10481.16,4107.77 ; 10481.16,4107.77 10495.57,4107.77 ; 10481.16,4107.77 10481.16,4107.67 10494.74,4094.1 ; 10494.74,4094.1 10508.4,4107.77 ; 10494.74,4094.1 10494.74,4106.93 10495.57,4107.77 ; 10495.57,4107.77 10508.4,4107.77
  Bottom Layer w10: v1@8993.82,4089.23 8993.82,3703.13 8993.82,2063.74 8843.61,1913.53 8843.61,892.27 8843.61,825.49 9318.76,350.34 10056.89,350.34 10925.92,350.34 10973.57,397.98 10973.57,498.79 R1.1@10597.59,874.77
  other v1: 8994.3,4081.49
NetR24_1: R24.1 R25.2 R26.2 R27.2 R28.2 R29.2 R30.2 R31.2 R32.2 R33.2 R34.2 R35.2 R36.2 R37.2 R38.2 R39.2 R40.2 R41.2 | length 17765
  Top Layer w10: R25.2@537.16,3251.67 537.16,3298.82 558.47,3320.13 1140.62,3320.13 ; R26.2@1150.83,3252.61 1150.83,3309.92 ; R27.2@1740.59,3253.07 1740.59,3308.43 ; R28.2@2340.59,3253.12 2340.59,3308.55 ; R29.2@2956.93,3252.16 2956.93,3310.03 ; R30.2@3558.19,3252.9 3558.19,3308.9 ; R31.2@4176.8,3253.05 4176.8,3307.47 ; R32.2@4770.6,3252.74 4770.6,3308.24 ; R33.2@5381.85,3252.04 5381.85,3309.02 ; R34.2@5970.17,3252.33 5970.17,3308.46 ; R35.2@6596.31,3252.61 6596.31,3306.71 ; R36.2@7194.8,3252.61 7194.8,3306.78 ; R37.2@7799.26,3252.61 7799.26,3309.21 ; R38.2@8690.87,3252.61 8690.87,3310.22 ; R39.2@9902.63,3252.32 9902.63,3310.58 ; R40.2@10493.89,3252.61 10493.89,3308.7 ; 10493.89,3316.32 10493.89,3308.7 ; R41.2@11116.24,3252.61 11116.24,3308.13 11104.24,3320.13 10506.47,3320.13 ; 1140.62,3320.13 1152.53,3320.13 ; 1140.62,3320.13 1150.83,3309.92 ; 1150.83,3309.92 1161.05,3320.13 ; 1150.83,3309.92 1150.83,3318.43 1152.53,3320.13 ; 1152.53,3320.13 1161.05,3320.13 ; 1161.05,3320.13 1728.89,3320.13 ; 1728.89,3320.13 1740.81,3320.13 ; 1728.89,3320.13 1740.59,3308.43 ; 1740.59,3308.43 1752.29,3320.13 ; 1740.59,3308.43 1740.59,3319.91 1740.81,3320.13 ; 1740.81,3320.13 1752.29,3320.13 ; 1752.29,3320.13 2329.01,3320.13 ; 2329.01,3320.13 2337.6,3320.13 ; 2329.01,3320.13 2340.59,3308.55 ; 2337.6,3320.13 2352.18,3320.13 ; 2337.6,3320.13 2340.59,3317.14 2340.59,3308.55 ; 2340.59,3308.55 2352.18,3320.13 ; 2352.18,3320.13 2946.82,3320.13 ; 2946.82,3320.13 2958.56,3320.13 ; 2946.82,3320.13 2956.93,3310.03 ; 2956.93,3310.03 2967.03,3320.13 ; 2956.93,3310.03 2956.93,3318.5 2958.56,3320.13 ; 2958.56,3320.13 2967.03,3320.13 ; 2967.03,3320.13 3546.96,3320.13 ; 3546.96,3320.13 3557.41,3320.13 ; 3546.96,3320.13 3558.19,3308.9 ; 3557.41,3320.13 3569.42,3320.13 ; 3557.41,3320.13 3558.19,3319.36 3558.19,3308.9 ; 3558.19,3308.9 3569.42,3320.13 ; 3569.42,3320.13 4165.1,3320.13 ; 4165.1,3320.13 4173.9,3320.13 ; 4165.1,3320.13 4165.1,3319.16 4176.8,3307.47 ; 4173.9,3320.13 4189.46,3320.13 ; 4173.9,3320.13 4176.8,3317.23 4176.8,3307.47 ; 4176.8,3307.47 4189.46,3320.13 ; 4189.46,3320.13 4758.71,3320.13 ; 4758.71,3320.13 4769.96,3320.13 ; 4758.71,3320.13 4770.6,3308.24 ; 4769.96,3320.13 4782.49,3320.13 ; 4769.96,3320.13 4770.6,3319.49 4770.6,3308.24 ; 4770.6,3308.24 4782.49,3320.13 ; 4782.49,3320.13 5370.74,3320.13 ; 5370.74,3320.13 5383.5,3320.13 ; 5370.74,3320.13 5381.85,3309.02 ; 5381.85,3309.02 5392.95,3320.13 ; 5381.85,3309.02 5381.85,3318.48 5383.5,3320.13 ; 5383.5,3320.13 5392.95,3320.13 ; 5392.95,3320.13 5959.24,3320.13 ; 5959.24,3320.13 5970.85,3320.13 ; 5959.24,3320.13 5959.24,3319.4 5970.17,3308.46 ; 5970.17,3308.46 5981.84,3320.13 ; 5970.17,3308.46 5970.17,3319.45 5970.85,3320.13 ; 5970.85,3320.13 5981.84,3320.13 ; 5981.84,3320.13 6582.89,3320.13 ; 6582.89,3320.13 6594.51,3320.13 ; 6582.89,3320.13 6596.31,3306.71 ; 6594.51,3320.13 6609.73,3320.13 ; 6594.51,3320.13 6596.31,3318.32 6596.31,3306.71 ; 6596.31,3306.71 6609.73,3320.13 ; 6609.73,3320.13 7181.45,3320.13 ; 7181.45,3320.13 7195.93,3320.13 ; 7181.45,3320.13 7194.8,3306.78 ; 7194.8,3306.78 7208.15,3320.13 ; 7194.8,3306.78 7194.8,3319 7195.93,3320.13 ; 7195.93,3320.13 7208.15,3320.13 ; 7208.15,3320.13 7789.28,3320.13 ; 7789.28,3320.13 7798.81,3320.13 ; 7789.28,3320.13 7789.28,3319.2 7799.26,3309.21 ; 7798.81,3320.13 7809.88,3320.13 ; 7798.81,3320.13 7799.26,3319.68 7799.26,3309.51 ; 7799.26,3309.21 7799.26,3309.51 ; 7799.26,3309.51 7809.88,3320.13 ; 7809.88,3320.13 8680.96,3320.13 ; 8680.96,3320.13 8688.93,3320.13 ; 8680.96,3320.13 8690.87,3310.22 ; 8688.93,3320.13 8700.78,3320.13 ; 8688.93,3320.13 8690.87,3318.19 8690.87,3310.22 ; 8690.87,3310.22 8700.78,3320.13 ; 8700.78,3320.13 9893.08,3320.13 ; 9893.08,3320.13 9902.42,3320.13 ; 9893.08,3320.13 9902.63,3310.58 ; 9902.42,3320.13 9912.18,3320.13 ; 9902.42,3320.13 9902.63,3319.92 9902.63,3310.58 ; 9902.63,3310.58 9912.18,3320.13 ; 9912.18,3320.13 10482.47,3320.13 ; 10482.47,3320.13 10506.47,3320.13 ; 10482.47,3320.13 10493.89,3308.7 ; 10493.89,3308.7 10495.05,3308.7 10506.47,3320.13
  Bottom Layer w10: v1(8936.2,3319.23) 8936.2,2081.76 8812.37,1957.93 8812.37,1339.5 8812.37,820.26 9305.54,327.09 10937.7,327.09 11006.07,395.47 11006.07,542.93 10729.58,819.42 R24.1@10729.58,874.77
NetR47_1: R47.1 R48.2 R49.2 R50.2 R51.2 R52.2 R53.2 R54.2 R55.2 R56.2 R57.2 R58.2 R59.2 R60.2 R61.2 R62.2 R63.2 R64.2 | length 16933.6
  Top Layer w10: R48.2@715.17,2648.31 715.17,2689.5 735.25,2709.58 1398.36,2709.58 ; R49.2@1409.4,2648.31 1409.4,2698.54 ; R50.2@2001.53,2649.63 2001.53,2699.15 ; R51.2@2620.64,2649.18 2620.64,2699.31 ; R52.2@3226.67,2648.1 3226.67,2698.42 ; R53.2@3829.5,2648.8 3829.5,2700.53 ; R54.2@4421.3,2648.31 4421.3,2699.11 ; R55.2@5038.65,2648.54 5038.65,2700.83 ; R56.2@5625.57,2648.53 5625.57,2699.55 ; R57.2@6243.24,2648.31 6243.24,2697.89 ; R58.2@6849.4,2648.31 6849.4,2695.33 ; R59.2@7460.77,2648.31 7460.77,2697.32 ; R60.2@8064.44,2648.31 8064.44,2698.83 ; R61.2@8874.7,2649.19 8874.7,2690.06 ; R62.2@9868.25,2648.31 9868.25,2698.8 ; R63.2@10483.15,2648.31 10483.15,2698.23 ; R64.2@11111.24,2648.43 11111.24,2693.33 11095,2709.58 10494.49,2709.58 ; 1398.36,2709.58 1410.47,2709.58 ; 1398.36,2709.58 1409.4,2698.54 ; 1409.4,2698.54 1420.44,2709.58 ; 1409.4,2698.54 1409.4,2708.5 1410.47,2709.58 ; 1410.47,2709.58 1420.44,2709.58 ; 1420.44,2709.58 1991.11,2709.58 ; 1991.11,2709.58 2001.05,2709.58 ; 1991.11,2709.58 2001.53,2699.15 ; 2001.05,2709.58 2011.96,2709.58 ; 2001.05,2709.58 2001.53,2709.09 2001.53,2699.15 ; 2001.53,2699.15 2011.96,2709.58 ; 2011.96,2709.58 2610.37,2709.58 ; 2610.37,2709.58 2621.01,2709.58 ; 2610.37,2709.58 2620.64,2699.31 ; 2620.64,2699.31 2630.92,2709.58 ; 2620.64,2699.31 2620.64,2709.21 2621.01,2709.58 ; 2621.01,2709.58 2630.92,2709.58 ; 2630.92,2709.58 3215.52,2709.58 ; 3215.52,2709.58 3227.01,2709.58 ; 3215.52,2709.58 3226.67,2698.42 ; 3226.67,2698.42 3237.83,2709.58 ; 3226.67,2698.42 3226.67,2709.24 3227.01,2709.58 ; 3227.01,2709.58 3237.83,2709.58 ; 3237.83,2709.58 3820.45,2709.58 ; 3820.45,2709.58 3829.33,2709.58 ; 3820.45,2709.58 3829.5,2700.53 ; 3829.33,2709.58 3838.55,2709.58 ; 3829.33,2709.58 3829.5,2709.41 3829.5,2700.53 ; 3829.5,2700.53 3838.55,2709.58 ; 3838.55,2709.58 4410.83,2709.58 ; 4410.83,2709.58 4420.59,2709.58 ; 4410.83,2709.58 4421.3,2699.11 ; 4420.59,2709.58 4431.77,2709.58 ; 4420.59,2709.58 4421.3,2708.87 4421.3,2699.11 ; 4421.3,2699.11 4431.77,2709.58 ; 4431.77,2709.58 5029.9,2709.58 ; 5029.9,2709.58 5038.65,2709.58 ; 5029.9,2709.58 5038.65,2700.83 ; 5038.65,2700.83 5047.4,2709.58 ; 5038.65,2700.83 5038.65,2709.58 ; 5038.65,2709.58 5047.4,2709.58 ; 5047.4,2709.58 5615.54,2709.58 ; 5615.54,2709.58 5624.04,2709.58 ; 5615.54,2709.58 5625.57,2699.55 ; 5624.04,2709.58 5635.59,2709.58 ; 5624.04,2709.58 5625.57,2708.05 5625.57,2699.55 ; 5625.57,2699.55 5635.59,2709.58 ; 5635.59,2709.58 6234.31,2709.58 ; 6234.31,2709.58 6242.56,2709.58 ; 6234.31,2709.58 6234.31,2706.82 6243.24,2697.89 ; 6242.56,2709.58 6254.92,2709.58 ; 6242.56,2709.58 6243.24,2708.9 6243.24,2697.89 ; 6243.24,2697.89 6254.92,2709.58 ; 6254.92,2709.58 6835.15,2709.58 ; 6835.15,2709.58 6852.34,2709.58 ; 6835.15,2709.58 6849.4,2695.33 ; 6849.4,2695.33 6863.64,2709.58 ; 6849.4,2695.33 6849.4,2706.64 6852.34,2709.58 ; 6852.34,2709.58 6863.64,2709.58 ; 6863.64,2709.58 7448.51,2709.58 ; 7448.51,2709.58 7457.74,2709.58 ; 7448.51,2709.58 7460.77,2697.32 ; 7457.74,2709.58 7473.03,2709.58 ; 7457.74,2709.58 7460.77,2706.55 7460.77,2697.32 ; 7460.77,2697.32 7473.03,2709.58 ; 7473.03,2709.58 8053.69,2709.58 ; 8053.69,2709.58 8065.78,2709.58 ; 8053.69,2709.58 8064.44,2698.83 ; 8064.44,2698.83 8075.18,2709.58 ; 8064.44,2698.83 8064.44,2708.23 8065.78,2709.58 ; 8065.78,2709.58 8075.18,2709.58 ; 8075.18,2709.58 8855.18,2709.58 ; 8855.18,2709.58 v1@8876.5,2709.58 ; 8855.18,2709.58 v1@8863.6,2701.16 ; v1@8863.6,2701.16 8874.7,2690.06 ; v1@8863.6,2701.16 8864.22,2701.78 v1@8874.7,2701.78 ; 8874.7,2690.06 v1@8886.42,2701.78 ; 8874.7,2690.06 v1@8874.7,2701.78 ; v1@8874.7,2701.78 v1@8886.42,2701.78 ; v1@8874.7,2701.78 8874.7,2707.78 v1@8876.5,2709.58 ; v1@8876.5,2709.58 8894.22,2709.58 ; v1@8886.42,2701.78 8894.22,2709.58 ; 8894.22,2709.58 9857.48,2709.58 ; 9857.48,2709.58 9869.79,2709.58 ; 9857.48,2709.58 9868.25,2698.8 ; 9868.25,2698.8 9879.03,2709.58 ; 9868.25,2698.8 9868.25,2708.04 9869.79,2709.58 ; 9869.79,2709.58 9879.03,2709.58 ; 9879.03,2709.58 10471.8,2709.58 ; 10471.8,2709.58 10480.94,2709.58 ; 10471.8,2709.58 10483.15,2698.23 ; 10480.94,2709.58 10494.49,2709.58 ; 10480.94,2709.58 10483.15,2707.38 10483.15,2698.23 ; 10483.15,2698.23 10494.49,2709.58
  Bottom Layer w10: v1@8876.5,2709.58 8876.5,2097.05 8782.22,2002.77 8782.22,814.63 9293.24,303.6 9935.61,303.6 10950.71,303.6 11035.72,388.61 11035.72,603.33 10862.22,776.83 R47.1@10862.22,888.14
  other v1: 8875.27,2708.64
NetR70_1: R70.1 R72.2 R73.2 R74.2 R75.2 R76.2 R77.2 R78.2 R79.2 R80.2 R81.2 R82.2 R83.2 | length 12474.5
  Top Layer w10: R72.2@1600.16,2031.99 1600.16,2074.33 1621.98,2096.15 2188.66,2096.15 ; R73.2@2196.92,2030.9 2196.92,2086.7 ; R74.2@2811.34,2032.03 2811.34,2084.04 ; R75.2@3414.88,2031.41 3414.88,2086.69 ; R76.2@4028.46,2031.83 4028.46,2087.33 ; R77.2@4625.22,2033.84 4625.22,2086.74 ; R78.2@5239.81,2034.04 5239.81,2085.99 ; R79.2@5841.13,2032.89 5841.13,2087.27 ; R80.2@6440.21,2032.89 6440.21,2085 ; R81.2@7042.27,2032.88 7042.27,2084.67 ; R82.2@7649.97,2029.77 7649.97,2084.86 ; R83.2@8589.85,2035.23 R83.2@8593.62,2031.46 v1(8593.62,2072.72) 8570.18,2096.15 7661.26,2096.15 ; 2188.66,2096.15 2196.73,2096.15 ; 2188.66,2096.15 2188.66,2094.96 2196.92,2086.7 ; 2196.73,2096.15 2206.61,2096.15 ; 2196.73,2096.15 2196.92,2095.97 2196.92,2086.7 ; 2196.92,2086.7 2197.16,2086.7 2206.61,2096.15 ; 2206.61,2096.15 2801.95,2096.15 ; 2801.95,2096.15 2815.01,2096.15 ; 2801.95,2096.15 2801.95,2093.43 2811.34,2084.04 ; 2811.34,2084.04 2823.45,2096.15 ; 2811.34,2084.04 2811.34,2092.48 2815.01,2096.15 ; 2815.01,2096.15 2823.45,2096.15 ; 2823.45,2096.15 3405.42,2096.15 ; 3405.42,2096.15 3415.49,2096.15 ; 3405.42,2096.15 3414.88,2086.69 ; 3414.88,2086.69 3424.34,2096.15 ; 3414.88,2086.69 3414.88,2095.55 3415.49,2096.15 ; 3415.49,2096.15 3424.34,2096.15 ; 3424.34,2096.15 4019,2096.15 ; 4019,2096.15 4028.29,2096.15 ; 4019,2096.15 4027.82,2087.33 ; 4027.82,2087.33 4028.46,2087.97 ; 4027.82,2087.33 4028.46,2087.33 ; 4028.29,2096.15 4036.64,2096.15 ; 4028.29,2096.15 4028.46,2095.99 4028.46,2087.97 ; 4028.46,2087.33 4028.46,2087.97 ; 4028.46,2087.97 4036.64,2096.15 ; 4036.64,2096.15 4615.8,2096.15 ; 4615.8,2096.15 4624.94,2096.15 ; 4615.8,2096.15 4625.22,2086.74 ; 4624.94,2096.15 4634.63,2096.15 ; 4624.94,2096.15 4625.22,2095.87 4625.22,2086.74 ; 4625.22,2086.74 4634.63,2096.15 ; 4634.63,2096.15 5229.65,2096.15 ; 5229.65,2096.15 5241.19,2096.15 ; 5229.65,2096.15 5239.81,2085.99 ; 5239.81,2085.99 5249.97,2096.15 ; 5239.81,2085.99 5239.81,2094.78 5241.19,2096.15 ; 5241.19,2096.15 5249.97,2096.15 ; 5249.97,2096.15 5832.25,2096.15 ; 5832.25,2096.15 5842.27,2096.15 ; 5832.25,2096.15 5841.13,2087.27 ; 5841.13,2087.27 5850.02,2096.15 ; 5841.13,2087.27 5841.13,2095.02 5842.27,2096.15 ; 5842.27,2096.15 5850.02,2096.15 ; 5850.02,2096.15 6429.06,2096.15 ; 6429.06,2096.15 6440.71,2096.15 ; 6429.06,2096.15 6440.21,2085 ; 6440.21,2085 6451.36,2096.15 ; 6440.21,2085 6440.21,2095.65 6440.71,2096.15 ; 6440.71,2096.15 6451.36,2096.15 ; 6451.36,2096.15 7030.79,2096.15 ; 7030.79,2096.15 7041.78,2096.15 ; 7030.79,2096.15 7042.27,2084.67 ; 7041.78,2096.15 7053.75,2096.15 ; 7041.78,2096.15 7042.27,2095.66 7042.27,2084.67 ; 7042.27,2084.67 7053.75,2096.15 ; 7053.75,2096.15 7639.25,2096.15 ; 7639.25,2096.15 7648.66,2096.15 ; 7639.25,2096.15 7639.25,2095.57 7649.97,2084.86 ; 7648.66,2096.15 7661.26,2096.15 ; 7648.66,2096.15 7649.97,2094.85 7649.97,2084.86 ; 7649.97,2084.86 7661.26,2096.15
  Bottom Layer w10: v1(8593.62,2072.72) 8593.62,1289.27 8593.62,963.01 9279.04,277.58 10959.25,277.58 11066.27,384.59 11066.27,662.95 10996.06,733.16 R70.1@10996.06,887.13
NetR90_1: R90.1 R91.2 R92.2 R93.2 R94.2 R95.2 R96.2 R97.2 R98.2 R99.2 R100.2 R101.2 R102.2 R104.2 | length 14667.2
  Top Layer w10: R91.2@908.57,1430.13 908.57,1474.53 930.42,1496.38 1863.45,1496.38 ; R92.2@1874.92,1430.13 1874.92,1484.91 ; R93.2@2478.02,1430.13 2478.02,1487.77 ; R94.2@3084.41,1430.13 3084.41,1484.31 ; R95.2@3681.97,1430.13 3681.97,1486.56 ; R96.2@4286.23,1430.13 4286.23,1485.56 ; R97.2@4897.28,1430.13 4897.28,1485.37 ; R98.2@5483.24,1430.13 5483.24,1486.5 ; R99.2@6112.64,1430.13 6112.64,1486.5 ; R100.2@6715.27,1430.5 6715.27,1483.67 ; 6715.27,1496.35 6715.27,1483.67 ; R101.2@7320.86,1428.03 7320.86,1485.96 ; R102.2@8317.72,1430.13 8317.72,1485.81 ; R104.2@10492.11,1430.13 10492.11,1463.22 10458.95,1496.38 8328.29,1496.38 ; 1863.45,1496.38 1878.25,1496.38 ; 1863.45,1496.38 1874.92,1484.91 ; 1874.92,1484.91 1877.18,1484.91 1888.65,1496.38 ; 1874.92,1484.91 1874.92,1493.05 1878.25,1496.38 ; 1878.25,1496.38 1888.65,1496.38 ; 1888.65,1496.38 2469.4,1496.38 ; 2469.4,1496.38 2478.02,1496.38 ; 2469.4,1496.38 2478.02,1487.77 ; 2478.02,1487.77 2486.63,1496.38 ; 2478.02,1487.77 2478.02,1496.38 ; 2478.02,1496.38 2486.63,1496.38 ; 2486.63,1496.38 3072.34,1496.38 ; 3072.34,1496.38 3086.56,1496.38 ; 3072.34,1496.38 3084.41,1484.31 ; 3084.41,1484.31 3096.48,1496.38 ; 3084.41,1484.31 3084.41,1494.23 3086.56,1496.38 ; 3086.56,1496.38 3096.48,1496.38 ; 3096.48,1496.38 3672.15,1496.38 ; 3672.15,1496.38 3681.52,1496.38 ; 3672.15,1496.38 3681.97,1486.56 ; 3681.52,1496.38 3691.79,1496.38 ; 3681.52,1496.38 3681.97,1495.93 3681.97,1486.56 ; 3681.97,1486.56 3691.79,1496.38 ; 3691.79,1496.38 4275.41,1496.38 ; 4275.41,1496.38 4283.84,1496.38 ; 4275.41,1496.38 4286.23,1485.56 ; 4283.84,1496.38 4297.05,1496.38 ; 4283.84,1496.38 4286.23,1493.99 4286.23,1485.56 ; 4286.23,1485.56 4297.05,1496.38 ; 4297.05,1496.38 4886.27,1496.38 ; 4886.27,1496.38 4894.45,1496.38 ; 4886.27,1496.38 4897.28,1485.37 ; 4894.45,1496.38 4908.28,1496.38 ; 4894.45,1496.38 4897.28,1493.56 4897.28,1485.37 ; 4897.28,1485.37 4908.28,1496.38 ; 4908.28,1496.38 5473.36,1496.38 ; 5473.36,1496.38 5483.91,1496.38 ; 5473.36,1496.38 5483.24,1486.5 ; 5483.24,1486.5 5493.11,1496.38 ; 5483.24,1486.5 5483.24,1495.71 5483.91,1496.38 ; 5483.91,1496.38 5493.11,1496.38 ; 5493.11,1496.38 6102.76,1496.38 ; 6102.76,1496.38 6114.75,1496.38 ; 6102.76,1496.38 6112.64,1486.5 ; 6112.64,1486.5 6122.51,1496.38 ; 6112.64,1486.5 6112.64,1494.27 6114.75,1496.38 ; 6114.75,1496.38 6122.51,1496.38 ; 6122.51,1496.38 6703.34,1496.38 ; 6703.34,1496.38 6715.25,1496.38 6727.98,1496.38 ; 6703.34,1496.38 6703.34,1495.6 6715.27,1483.67 ; 6715.27,1483.67 6727.98,1496.38 ; 6727.98,1496.38 7310.45,1496.38 ; 7310.45,1496.38 7322.19,1496.38 ; 7310.45,1496.38 7320.86,1485.96 ; 7320.86,1485.96 7331.28,1496.38 ; 7320.86,1485.96 7320.86,1495.05 7322.19,1496.38 ; 7322.19,1496.38 7331.28,1496.38 ; 7331.28,1496.38 8307.14,1496.38 ; 8307.14,1496.38 8315.33,1496.38 ; 8307.14,1496.38 8317.72,1485.81 ; 8315.33,1496.38 8328.29,1496.38 ; 8315.33,1496.38 8317.72,1493.99 8317.72,1485.81 ; 8317.72,1485.81 8328.29,1496.38
  Bottom Layer w10: v1(8548.93,1495.84) 8548.93,970.17 9263.07,256.03 10047.81,256.03 10972.27,256.03 11093.63,377.39 11093.63,666.49 11127.18,700.04 R90.1@11127.18,859.13
NetR110_1: R110.1 R111.2 R112.2 R113.2 R114.2 R115.2 R118.2 R119.2 R122.2 R123.2 R124.2 R_Fn.2 | length 11512.1
  Top Layer w10: R111.2@609.35,828.35 609.35,859.45 626.9,877 1377.6,877 ; R112.2@1386.96,820.21 1386.96,866.6 ; R113.2@2140.73,826.72 2140.73,867.42 ; R114.2@4378.57,822.75 4378.57,868.01 ; R115.2@6655.5,828.74 6655.5,866.16 ; R_Fn.2@7408.81,828.57 7408.81,867.67 ; R118.2@8203.18,830.64 8203.18,867.75 ; R119.2@8973.69,826.13 8973.69,866.57 ; R122.2@9881.14,829.67 9881.14,865.18 ; R123.2@10494.1,821.07 10494.1,865.72 ; v1@11264.49,827.9 R124.2@11091.31,827.9 11091.31,862.18 11076.5,877 10505.37,877 ; 1377.6,877 1386.96,877 ; 1377.6,877 1377.6,875.96 1386.96,866.6 ; 1386.96,866.6 1397.36,877 ; 1386.96,866.6 1386.96,877 ; 1386.96,877 1397.36,877 ; 1397.36,877 2131.15,877 ; 2131.15,877 2140.73,877 ; 2131.15,877 2140.73,867.42 ; 2140.73,867.42 2150.31,877 ; 2140.73,867.42 2140.73,877 ; 2140.73,877 2150.31,877 ; 2150.31,877 4369.58,877 ; 4369.58,877 4378.57,877 ; 4369.58,877 4378.57,868.01 ; 4378.57,868.01 4387.56,877 ; 4378.57,868.01 4378.57,877 ; 4378.57,877 4387.56,877 ; 4387.56,877 6644.66,877 ; 6644.66,877 6655.5,877 ; 6644.66,877 6655.5,866.16 ; 6655.5,866.16 6666.34,877 ; 6655.5,866.16 6655.5,877 ; 6655.5,877 6666.34,877 ; 6666.34,877 7399.48,877 ; 7399.48,877 7407.62,877 ; 7399.48,877 7408.81,867.67 ; 7407.62,877 7418.14,877 ; 7407.62,877 7408.81,875.81 7408.81,867.67 ; 7408.81,867.67 7418.14,877 ; 7418.14,877 8193.93,877 ; 8193.93,877 8203.18,877 ; 8193.93,877 8203.18,867.75 ; 8203.18,867.75 8212.43,877 ; 8203.18,867.75 8203.18,877 ; 8203.18,877 8212.43,877 ; 8212.43,877 8963.27,877 ; 8963.27,877 8973.69,877 ; 8963.27,877 8973.69,866.57 ; 8973.69,866.57 8984.12,877 ; 8973.69,866.57 8973.69,877 ; 8973.69,877 8984.12,877 ; 8984.12,877 9869.32,877 ; 9869.32,877 9881.14,877 ; 9869.32,877 9881.14,865.18 ; 9881.14,865.18 9881.14,865.34 ; 9881.14,865.34 9881.14,877 ; 9881.14,865.34 9892.8,877 ; 9881.14,877 9892.8,877 ; 9892.8,877 10482.82,877 ; 10482.82,877 10494.1,877 ; 10482.82,877 10494.1,865.72 ; 10494.1,865.72 10505.37,877 ; 10494.1,865.72 10494.1,877 ; 10494.1,877 10505.37,877
  Bottom Layer w10: v1@11262.15,826.97 R110.1@11262.15,886.9
  other v1: 11262.28,828.32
